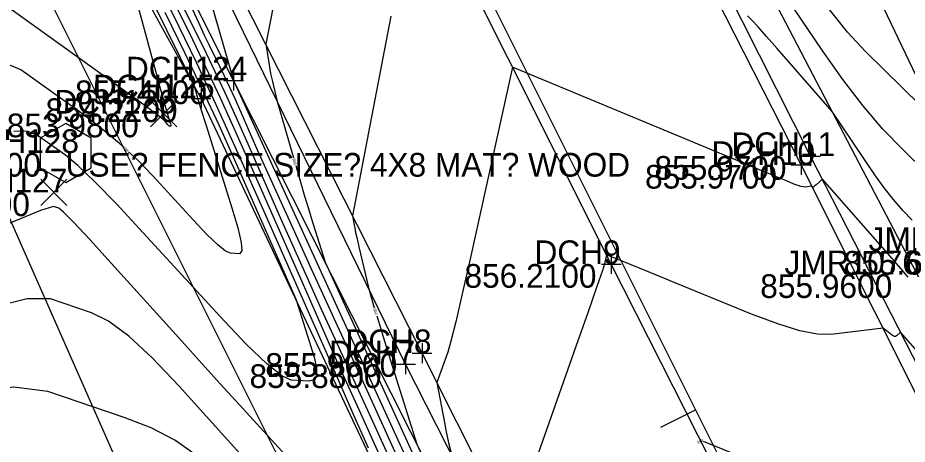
# Model space of a CAD drawing. Extents: x 1654928 to 1810050, y 486881 to 626330.
# Drawn here: x 1801482.75 to 1801527.86, y 489650.35 to 489671.96 of the extents above; entities that cross this region are included whole.
import ezdxf

# ---------------------------------------------------------------- set-up
doc = ezdxf.new("R2010")
doc.units = 0
for name, color, linetype in [('DR_X_Ditch', 7, 'Continuous'), ('DT_X_Contour_Major', 7, 'Continuous'), ('DT_X_Contour_Minor', 7, 'Continuous'), ('PV_X_EOP', 7, 'Continuous'), ('PV_X_Shoulder', 7, 'Continuous'), ('RD_X_Cells', 7, 'Continuous'), ('RW_X_Esmt_SH', 7, 'Continuous'), ('SV_X_Break_Lines', 7, 'Continuous'), ('SV_X_Center_of_Pavt', 7, 'Continuous'), ('SV_X_CL_Survey_20', 7, 'Continuous'), ('SV_X_Occupation_Line', 7, 'Continuous'), ('SV_X_Random_Point', 7, 'Continuous'), ('SV_X_Shot_Marker', 7, 'Continuous'), ('SV_X_Text_Comment', 7, 'Continuous'), ('SV_X_Text_Elevation', 7, 'Continuous'), ('SV_X_Text_Name', 7, 'Continuous')]:
    doc.layers.add(name, color=color, linetype=linetype)

msp = doc.modelspace()

# ---------------------------------------------------------------- linework, layer by layer
at = {"layer": 'DR_X_Ditch'}
msp.add_lwpolyline([(1801540.062, 489643.432), (1801532.556, 489660.144), (1801517.868, 489690.883), (1801504.345, 489723.544), (1801491.469, 489750.565), (1801478.102, 489779.895), (1801464.666, 489805.356), (1801460.448, 489815.434)], dxfattribs=at)
at = {"layer": 'DT_X_Contour_Major'}
for points in [[(1801483.834, 489690.01), (1801483.96, 489689.598), (1801484.138, 489689.008), (1801484.29, 489688.491), (1801484.934, 489686.256), (1801488.73, 489677.755), (1801489.494, 489676.055), (1801490.159, 489674.6), (1801490.725, 489673.389), (1801491.192, 489672.422), (1801492.305, 489670.169), (1801492.751, 489669.248), (1801493.252, 489668.174), (1801493.81, 489666.948), (1801494.424, 489665.569), (1801496.136, 489661.689), (1801496.787, 489660.22), (1801497.456, 489658.724), (1801498.144, 489657.201), (1801498.851, 489655.65), (1801500.759, 489651.477), (1801501.522, 489649.806)], [(1801482.136, 489687.22), (1801482.968, 489685.483), (1801483.868, 489683.644), (1801488.226, 489674.825), (1801489.686, 489669.469), (1801489.964, 489668.451), (1801490.31, 489667.197), (1801490.379, 489666.96), (1801490.468, 489666.676), (1801490.496, 489666.582), (1801490.511, 489666.516), (1801490.513, 489666.476), (1801490.504, 489666.464), (1801490.461, 489666.466), (1801490.439, 489666.476), (1801490.402, 489666.505), (1801490.353, 489666.553), (1801490.29, 489666.619), (1801490.104, 489666.822), (1801489.83, 489667.041), (1801489.146, 489667.548), (1801488.052, 489668.342), (1801486.55, 489669.424), (1801481.996, 489672.691)], [(1801527.914, 489658.821), (1801527.212, 489659.629), (1801523.558, 489663.79), (1801523.241, 489663.494), (1801523.18, 489663.44), (1801523.133, 489663.403), (1801523.1, 489663.385), (1801523.081, 489663.385), (1801523.026, 489663.428), (1801522.68, 489663.387), (1801522.592, 489663.388), (1801522.475, 489663.412), (1801522.33, 489663.456), (1801522.157, 489663.522), (1801521.656, 489663.726), (1801521.24, 489663.898), (1801520.367, 489664.26), (1801519.038, 489664.813), (1801507.851, 489669.47), (1801505.712, 489659.822), (1801505.296, 489657.972), (1801504.966, 489656.555), (1801504.72, 489655.572), (1801504.56, 489655.022), (1801504.012, 489653.471), (1801504.392, 489651.45), (1801504.467, 489651.057), (1801504.529, 489650.744), (1801504.577, 489650.512), (1801504.612, 489650.36), (1801504.744, 489649.837)], [(1801491.749, 489649.836), (1801490.721, 489650.553), (1801489.523, 489651.178), (1801488.155, 489651.712), (1801484.278, 489653.014), (1801482.547, 489653.242), (1801480.885, 489653.029)]]:
    msp.add_lwpolyline(points, dxfattribs=at)
at = {"layer": 'DT_X_Contour_Minor'}
for points in [[(1801480.552, 489694.99), (1801486.245, 489682.239), (1801487.391, 489679.69), (1801488.388, 489677.507), (1801489.237, 489675.69), (1801489.938, 489674.24), (1801491.608, 489670.86), (1801492.276, 489669.478), (1801493.029, 489667.868), (1801493.866, 489666.029), (1801494.786, 489663.96), (1801497.354, 489658.14), (1801498.244, 489656.126), (1801498.99, 489654.448), (1801499.59, 489653.106), (1801500.045, 489652.101), (1801501.066, 489649.869)], [(1801481.238, 489692.372), (1801484.538, 489684.98), (1801485.726, 489682.344), (1801486.813, 489679.978), (1801487.799, 489677.882), (1801488.684, 489676.057), (1801490.911, 489671.551), (1801491.802, 489669.709), (1801492.805, 489667.562), (1801493.921, 489665.109), (1801495.149, 489662.352), (1801498.572, 489654.591), (1801499.702, 489652.031), (1801500.523, 489650.172)], [(1801481.963, 489688.586), (1801482.861, 489686.608), (1801483.846, 489684.499), (1801484.92, 489682.258), (1801486.08, 489679.886), (1801491.702, 489668.511), (1801491.835, 489668.024), (1801491.906, 489667.786), (1801492.062, 489667.281), (1801492.304, 489666.508), (1801492.631, 489665.468), (1801493.615, 489662.339), (1801493.917, 489661.313), (1801494.082, 489660.582), (1801494.111, 489660.148), (1801494.005, 489660.008), (1801493.539, 489660.03), (1801493.29, 489660.142), (1801492.893, 489660.461), (1801492.348, 489660.986), (1801491.655, 489661.718), (1801489.61, 489663.947), (1801488.8, 489664.778), (1801488.365, 489665.176)], [(1801532.277, 489660.73), (1801527.635, 489665.281), (1801526.634, 489666.327), (1801525.62, 489667.515), (1801524.594, 489668.845), (1801523.554, 489670.318), (1801518.673, 489677.52)], [(1801496.289, 489675.598), (1801495.334, 489670.621), (1801495.501, 489669.583), (1801495.538, 489669.363), (1801495.578, 489669.149), (1801495.621, 489668.939), (1801495.668, 489668.733), (1801495.89, 489667.788), (1801496.733, 489664.874)], [(1801492.278, 489673.719), (1801493.699, 489668.787), (1801501.471, 489651.792), (1801502.684, 489649.13)], [(1801491.597, 489672.421), (1801491.929, 489671.694), (1801492.212, 489671.088), (1801492.445, 489670.605), (1801493.002, 489669.478), (1801493.225, 489669.017), (1801493.476, 489668.481), (1801493.755, 489667.868), (1801494.062, 489667.178), (1801494.918, 489665.238), (1801495.329, 489664.315), (1801495.923, 489663.001), (1801496.699, 489661.295), (1801497.656, 489659.198), (1801500.452, 489653.085), (1801501.541, 489650.701), (1801502.709, 489648.135)], [(1801529.479, 489666.585), (1801525.739, 489670.252), (1801524.834, 489671.24), (1801523.723, 489672.631)], [(1801490.214, 489672.242), (1801491.213, 489670.2), (1801492.122, 489668.298), (1801492.942, 489666.535), (1801493.672, 489664.912), (1801496.868, 489657.666), (1801497.782, 489654.764), (1801497.911, 489654.222), (1801497.908, 489653.84), (1801497.773, 489653.616), (1801497.506, 489653.553), (1801496.616, 489653.595), (1801496.141, 489653.808), (1801495.384, 489654.416), (1801494.343, 489655.42), (1801493.02, 489656.818), (1801489.116, 489661.072), (1801487.771, 489662.514), (1801486.665, 489663.648), (1801485.797, 489664.475), (1801485.169, 489664.994), (1801483.811, 489665.969), (1801483.241, 489666.21), (1801482.549, 489666.202)], [(1801501.681, 489672.053), (1801499.737, 489661.923), (1801499.812, 489661.462), (1801499.839, 489661.319), (1801499.889, 489661.086), (1801499.962, 489660.764), (1801500.058, 489660.353), (1801500.558, 489658.226), (1801500.836, 489657.265)], [(1801528.11, 489661.703), (1801527.635, 489662.198), (1801527.162, 489662.747), (1801526.693, 489663.352), (1801526.226, 489664.01), (1801524.057, 489667.211), (1801521.272, 489670.407), (1801520.73, 489671.023), (1801520.299, 489671.504), (1801519.979, 489671.848), (1801519.769, 489672.056)], [(1801488.056, 489665.46), (1801487.905, 489665.598), (1801486.925, 489666.409), (1801485.859, 489667.209), (1801482.903, 489669.33), (1801481.663, 489669.855), (1801480.158, 489669.839), (1801478.39, 489669.282), (1801476.357, 489668.184), (1801470.584, 489664.535), (1801468.411, 489663.217), (1801466.219, 489661.997), (1801464.009, 489660.877), (1801461.782, 489659.856), (1801455.818, 489657.265), (1801453.791, 489656.363), (1801452.182, 489655.602), (1801450.991, 489654.98), (1801450.22, 489654.498), (1801448.719, 489653.398), (1801447.798, 489652.705), (1801446.161, 489651.45), (1801443.807, 489649.633)], [(1801496.85, 489664.471), (1801496.901, 489664.291), (1801497.11, 489663.575), (1801497.302, 489662.926), (1801497.478, 489662.343), (1801497.637, 489661.827), (1801498.342, 489659.574), (1801501.79, 489652.035), (1801502.499, 489650.483), (1801503.737, 489647.764)], [(1801497.063, 489648.999), (1801494.869, 489651.39), (1801493.996, 489652.345), (1801493.021, 489653.415), (1801491.944, 489654.601), (1801490.767, 489655.903), (1801487.491, 489659.529), (1801486.403, 489660.723), (1801485.597, 489661.585), (1801485.073, 489662.117), (1801484.831, 489662.316), (1801484.561, 489662.407), (1801483.905, 489662.191), (1801482.14, 489661.473), (1801479.267, 489660.254), (1801475.286, 489658.534), (1801463.19, 489653.28), (1801459.07, 489651.445), (1801455.783, 489649.883)], [(1801529.852, 489653.384), (1801527.526, 489656.032), (1801527.324, 489655.844), (1801527.275, 489655.817), (1801527.214, 489655.818), (1801527.142, 489655.846), (1801527.058, 489655.902), (1801526.639, 489656.228), (1801523.988, 489655.912), (1801523.31, 489655.926), (1801522.416, 489656.104), (1801521.303, 489656.445), (1801519.972, 489656.95), (1801516.133, 489658.516), (1801514.862, 489659.035), (1801513.326, 489659.662), (1801513.062, 489659.77), (1801512.615, 489659.956), (1801512.513, 489659.497), (1801512.405, 489659.161), (1801512.128, 489658.352), (1801511.679, 489657.068), (1801511.06, 489655.31), (1801507.771, 489645.999)], [(1801494.783, 489649.037), (1801490.935, 489653.297), (1801489.575, 489654.728), (1801488.381, 489655.824), (1801487.354, 489656.586), (1801486.493, 489657.014), (1801484.419, 489657.711), (1801483.226, 489657.716), (1801481.201, 489657.211), (1801478.344, 489656.195), (1801474.656, 489654.667), (1801463.712, 489649.913)], [(1801500.956, 489656.862), (1801501.091, 489656.423), (1801501.303, 489655.739), (1801501.575, 489654.867), (1801502.984, 489650.36), (1801503.526, 489649.175), (1801503.611, 489648.989), (1801503.687, 489648.82), (1801503.756, 489648.668), (1801504.736, 489646.515), (1801505.645, 489644.519), (1801506.892, 489641.782), (1801510.667, 489633.497), (1801511.825, 489630.734), (1801512.468, 489628.661), (1801512.596, 489627.277), (1801512.209, 489626.582), (1801509.199, 489624.947)], [(1801521.434, 489648.891), (1801517.527, 489650.485)]]:
    msp.add_lwpolyline(points, dxfattribs=at)
at = {"layer": 'PV_X_EOP'}
for points in [[(1801533.684, 489642.188), (1801522.484, 489664.508), (1801511.881, 489685.341), (1801500.299, 489708.684), (1801491.104, 489726.659), (1801480.832, 489747.383), (1801466.882, 489774.659), (1801456.506, 489795.715), (1801444.637, 489819.009), (1801433.258, 489841.444), (1801422.029, 489863.995), (1801410.905, 489885.928), (1801399.817, 489908.089), (1801388.576, 489930.656), (1801376.228, 489955.188), (1801366.008, 489975.62), (1801354.725, 489997.894)], [(1801513.785, 489634.043), (1801503.26, 489654.965), (1801492.692, 489675.84), (1801481.803, 489697.704), (1801472.078, 489717.629), (1801460.782, 489739.414), (1801448.005, 489764.97), (1801436.553, 489786.89), (1801425.237, 489809.697), (1801414.345, 489830.894), (1801402.21, 489854.742), (1801391.781, 489876.056), (1801380.008, 489899.32), (1801369.395, 489920.807), (1801356.62, 489946.308), (1801346.845, 489965.404), (1801335.257, 489988.444)]]:
    msp.add_lwpolyline(points, dxfattribs=at)
at = {"layer": 'PV_X_Shoulder'}
for points in [[(1801534.471, 489642.456), (1801522.963, 489664.954), (1801512.6, 489685.485), (1801500.973, 489709.112), (1801491.766, 489727.019), (1801481.526, 489747.768), (1801467.484, 489775.07), (1801457.116, 489796.092), (1801445.57, 489819.398), (1801434.029, 489841.927), (1801422.682, 489864.343), (1801411.885, 489886.25), (1801400.664, 489908.455), (1801366.703, 489976.232), (1801355.676, 489998.276)], [(1801513.053, 489633.484), (1801502.425, 489654.401), (1801492.155, 489675.438), (1801481.048, 489697.245), (1801471.095, 489717.056), (1801459.974, 489738.844), (1801446.996, 489764.517), (1801435.938, 489786.184), (1801424.33, 489809.156), (1801413.386, 489830.353), (1801401.606, 489854.259), (1801390.811, 489875.349), (1801379.301, 489898.985), (1801368.607, 489920.204), (1801355.561, 489945.921), (1801346.174, 489964.922), (1801334.144, 489988.199)]]:
    msp.add_lwpolyline(points, dxfattribs=at)
at = {"layer": 'RD_X_Cells'}
msp.add_lwpolyline([(1801483.885, 489664.363), (1801485.183, 489663.613), (1801486.481, 489664.363), (1801486.481, 489665.863), (1801485.183, 489666.613), (1801483.885, 489665.863), (1801483.885, 489664.363)], dxfattribs=at)
at = {"layer": 'RW_X_Esmt_SH'}
msp.add_line((1801533.563, 489574.54), (1801308.538, 490024.454), dxfattribs=at)
at = {"layer": 'SV_X_Break_Lines'}
for points in [[(1801537.196, 489641.719), (1801528.364, 489658.964), (1801513.29, 489687.828), (1801498.001, 489720.37), (1801485.256, 489748.381), (1801470.065, 489776.956), (1801457.973, 489802.299), (1801452.712, 489809.925), (1801448.007, 489818.919)], [(1801514.716, 489627.856), (1801503.68, 489648.978), (1801493.699, 489668.787), (1801479.018, 489698.047), (1801467.542, 489721.318), (1801456.644, 489742.996), (1801445.175, 489766.173)], [(1801512.299, 489626.717), (1801501.419, 489648.021), (1801492.05, 489667.879), (1801476.233, 489696.609), (1801465.038, 489719.932)]]:
    msp.add_lwpolyline(points, dxfattribs=at)
at = {"layer": 'SV_X_Center_of_Pavt'}
msp.add_lwpolyline([(1801523.585, 489638.313), (1801512.853, 489659.481), (1801502.374, 489680.412), (1801490.819, 489703.952), (1801481.428, 489721.68), (1801470.803, 489742.834), (1801457.335, 489769.613), (1801446.389, 489792.464), (1801435.307, 489813.792), (1801423.54, 489836.522), (1801412.234, 489859.298), (1801401.202, 489881.345), (1801390.005, 489903.67), (1801378.784, 489926.715), (1801366.669, 489950.371), (1801356.567, 489970.63), (1801345.517, 489992.708)], dxfattribs=at)
at = {"layer": 'SV_X_CL_Survey_20'}
for p, q in [((1802886.975, 486913.246), (1801128.538, 490429.055)), ((1802886.975, 486913.246), (1801128.538, 490429.055)), ((1801517.141, 489652.085), (1801515.352, 489651.19))]:
    msp.add_line(p, q, dxfattribs=at)
at = {"layer": 'SV_X_Occupation_Line'}
msp.add_lwpolyline([(1801317.131, 489768.671), (1801358.983, 489768.588), (1801397.909, 489769.246), (1801416.492, 489765.323), (1801429.827, 489757.814), (1801441.541, 489745.071), (1801453.578, 489722.317), (1801464.849, 489700.041), (1801476.834, 489674.228), (1801497.657, 489627.098)], dxfattribs=at)
at = {"layer": 'SV_X_Random_Point'}
for p, q in [((1801489.487, 489666.442), (1801490.82, 489667.777)), ((1801489.487, 489667.777), (1801490.82, 489666.442)), ((1801483.915, 489662.444), (1801485.248, 489663.779)), ((1801483.915, 489663.779), (1801485.248, 489662.444))]:
    msp.add_line(p, q, dxfattribs=at)
at = {"layer": 'SV_X_Shot_Marker'}
for p, q in [((1801493.699, 489669.287), (1801493.699, 489668.287)), ((1801493.199, 489668.787), (1801494.199, 489668.787)), ((1801493.699, 489668.787), (1801493.699, 489668.787)), ((1801492.05, 489668.379), (1801492.05, 489667.379)), ((1801491.55, 489667.879), (1801492.55, 489667.879)), ((1801492.05, 489667.879), (1801492.05, 489667.879)), ((1801522.963, 489665.454), (1801522.963, 489664.454)), ((1801522.463, 489664.954), (1801523.463, 489664.954)), ((1801522.484, 489665.008), (1801522.484, 489664.008)), ((1801522.963, 489664.954), (1801522.963, 489664.954)), ((1801521.984, 489664.508), (1801522.984, 489664.508)), ((1801522.484, 489664.508), (1801522.484, 489664.508)), ((1801512.853, 489659.981), (1801512.853, 489658.981)), ((1801512.353, 489659.481), (1801513.353, 489659.481)), ((1801512.853, 489659.481), (1801512.853, 489659.481)), ((1801503.26, 489655.465), (1801503.26, 489654.465)), ((1801502.425, 489654.901), (1801502.425, 489653.901)), ((1801502.76, 489654.965), (1801503.76, 489654.965)), ((1801503.26, 489654.965), (1801503.26, 489654.965)), ((1801501.925, 489654.401), (1801502.925, 489654.401)), ((1801502.425, 489654.401), (1801502.425, 489654.401))]:
    msp.add_line(p, q, dxfattribs=at)

# ---------------------------------------------------------------- texts
at = {"layer": 'DT_X_Contour_Minor'}
for s, rotation, p in [('854', 137.4847, (1801488.375, 489665.263)), ('856', 286.1355, (1801496.678, 489664.81)), ('856', 286.631, (1801500.782, 489657.2)), ('856', 211.4202, (1801517.459, 489650.64))]:
    msp.add_text(s, height=0.14, rotation=rotation, dxfattribs=at).set_placement(p)
at = {"layer": 'SV_X_Text_Comment'}
msp.add_text('USE? FENCE SIZE? 4X8 MAT? WOOD', height=1.2, dxfattribs=at).set_placement((1801485.183, 489663.913))
at = {"layer": 'SV_X_Text_Elevation'}
for s, p in [('855.4000', (1801485.659, 489667.587)), ('854.2200', (1801484.161, 489666.679)), ('853.9800', (1801482.198, 489665.909)), ('854.4400', (1801477.237, 489663.913)), ('855.9700', (1801515.046, 489663.754)), ('855.9700', (1801514.567, 489663.308)), ('854.5700', (1801476.674, 489661.912)), ('855.6200', (1801524.639, 489658.944)), ('856.2100', (1801505.408, 489658.281)), ('855.9600', (1801520.409, 489657.764)), ('855.9600', (1801495.305, 489653.765)), ('855.8800', (1801494.507, 489653.201))]:
    msp.add_text(s, height=1.2, dxfattribs=at).set_placement(p)
at = {"layer": 'SV_X_Text_Name'}
for s, p in [('DCH124', (1801488.239, 489668.787)), ('DCH125', (1801486.58, 489667.879)), ('DCH126', (1801484.608, 489667.109)), ('DCH128', (1801479.704, 489665.113)), ('DCH11', (1801518.948, 489664.954)), ('DCH10', (1801517.931, 489664.508)), ('DCH127', (1801479.112, 489663.112)), ('JMR1075', (1801525.905, 489660.144)), ('DCH9', (1801508.96, 489659.481)), ('JMR1076', (1801521.638, 489658.964)), ('DCH8', (1801499.368, 489654.965)), ('DCH7', (1801498.542, 489654.401))]:
    msp.add_text(s, height=1.2, dxfattribs=at).set_placement(p)

doc.saveas('drawing.dxf')
